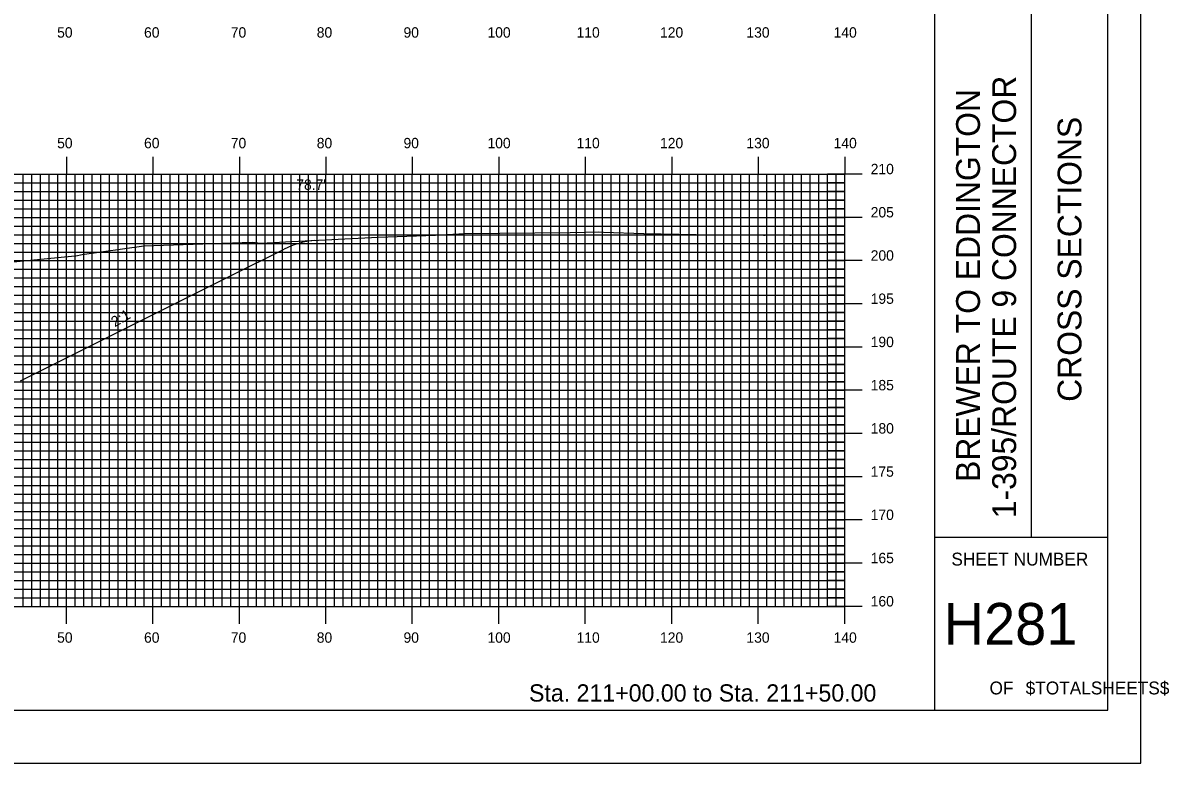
# Model space of a CAD drawing. Extents: x 1794846 to 1795189, y 442591 to 442811.
# Drawn here: x 1795056.8 to 1795189.3, y 442590.5 to 442676.2 of the extents above; entities that cross this region are included whole.
import ezdxf

# ---------------------------------------------------------------- set-up
doc = ezdxf.new("R2010")
doc.units = 0
for name, color, linetype in [('ANNOTATION', 7, 'Continuous'), ('BORDER', 7, 'Continuous'), ('D_Roadway_Centerline', 7, 'Continuous'), ('D_Roadway_SlopeLines', 7, 'Continuous'), ('D_Text_Standard', 7, 'Continuous'), ('H_V ANNOTATION', 7, 'Continuous'), ('MAJOR', 7, 'Continuous'), ('MINOR', 7, 'Continuous'), ('PLOT BOUNDARY', 7, 'Continuous'), ('S_Roadway_Centerline', 7, 'Continuous')]:
    doc.layers.add(name, color=color, linetype=linetype)

msp = doc.modelspace()

# ---------------------------------------------------------------- linework, layer by layer
at = {"layer": 'BORDER'}
for p, q in [((1795162.25, 442596.67), (1795162.25, 442806.67)), ((1795173.43, 442616.67), (1795173.43, 442686.67)), ((1795162.25, 442616.67), (1795182.25, 442616.67))]:
    msp.add_line(p, q, dxfattribs=at)
msp.add_lwpolyline([(1794862.25, 442596.67), (1795182.25, 442596.67), (1795182.25, 442806.67), (1794862.25, 442806.67)], close=True, dxfattribs=at)
at = {"layer": 'D_Roadway_Centerline'}
msp.add_arc((1795091.51, 442641.06), 10, 95.4173, 116.5651, dxfattribs=at)
at = {"layer": 'D_Roadway_SlopeLines'}
for p, q in [((1795080.92, 442646.94), (1795087.03, 442650)), ((1795056.56, 442634.77), (1795080.92, 442646.94))]:
    msp.add_line(p, q, dxfattribs=at)
at = {"layer": 'MAJOR'}
for p, q in [((1795061.85, 442660.67), (1795061.85, 442658.67)), ((1795071.85, 442660.67), (1795071.85, 442658.67)), ((1795081.85, 442660.67), (1795081.85, 442658.67)), ((1795091.85, 442660.67), (1795091.85, 442658.67)), ((1795101.85, 442660.67), (1795101.85, 442658.67)), ((1795111.85, 442660.67), (1795111.85, 442658.67)), ((1795121.85, 442660.67), (1795121.85, 442658.67)), ((1795131.85, 442660.67), (1795131.85, 442658.67)), ((1795141.85, 442660.67), (1795141.85, 442658.67)), ((1795151.85, 442660.67), (1795151.85, 442658.67)), ((1794871.85, 442658.67), (1795151.85, 442658.67)), ((1794871.85, 442658.67), (1795151.85, 442658.67)), ((1795061.85, 442608.67), (1795061.85, 442658.67)), ((1795071.85, 442608.67), (1795071.85, 442658.67)), ((1795081.85, 442608.67), (1795081.85, 442658.67)), ((1795091.85, 442608.67), (1795091.85, 442658.67)), ((1795101.85, 442608.67), (1795101.85, 442658.67)), ((1795111.85, 442608.67), (1795111.85, 442658.67)), ((1795121.85, 442608.67), (1795121.85, 442658.67)), ((1795131.85, 442608.67), (1795131.85, 442658.67)), ((1795141.85, 442608.67), (1795141.85, 442658.67)), ((1795153.86, 442658.67), (1795149.85, 442658.67)), ((1795151.85, 442608.67), (1795151.85, 442658.67)), ((1795151.85, 442608.67), (1795151.85, 442658.67)), ((1794871.85, 442653.67), (1795151.85, 442653.67)), ((1795153.86, 442653.67), (1795149.85, 442653.67)), ((1794871.85, 442648.67), (1795151.85, 442648.67)), ((1795153.86, 442648.67), (1795149.85, 442648.67)), ((1794871.85, 442643.67), (1795151.85, 442643.67)), ((1795153.86, 442643.67), (1795149.85, 442643.67)), ((1794871.85, 442638.67), (1795151.85, 442638.67)), ((1795153.86, 442638.67), (1795149.85, 442638.67)), ((1794871.85, 442633.67), (1795151.85, 442633.67)), ((1795153.86, 442633.67), (1795149.85, 442633.67)), ((1794871.85, 442628.67), (1795151.85, 442628.67)), ((1795153.86, 442628.67), (1795149.85, 442628.67)), ((1794871.85, 442623.67), (1795151.85, 442623.67)), ((1795153.86, 442623.67), (1795149.85, 442623.67)), ((1794871.85, 442618.67), (1795151.85, 442618.67)), ((1795153.86, 442618.67), (1795149.85, 442618.67)), ((1794871.85, 442613.67), (1795151.85, 442613.67)), ((1795153.86, 442613.67), (1795149.85, 442613.67)), ((1794871.85, 442608.67), (1795151.85, 442608.67)), ((1794871.85, 442608.67), (1795151.85, 442608.67)), ((1795061.85, 442606.66), (1795061.85, 442608.67)), ((1795071.85, 442606.66), (1795071.85, 442608.67)), ((1795081.85, 442606.66), (1795081.85, 442608.67)), ((1795091.85, 442606.66), (1795091.85, 442608.67)), ((1795101.85, 442606.66), (1795101.85, 442608.67)), ((1795111.85, 442606.66), (1795111.85, 442608.67)), ((1795121.85, 442606.66), (1795121.85, 442608.67)), ((1795131.85, 442606.66), (1795131.85, 442608.67)), ((1795141.85, 442606.66), (1795141.85, 442608.67)), ((1795153.86, 442608.67), (1795149.85, 442608.67)), ((1795151.85, 442606.66), (1795151.85, 442608.67))]:
    msp.add_line(p, q, dxfattribs=at)
at = {"layer": 'MINOR'}
for p, q in [((1795056.85, 442608.67), (1795056.85, 442658.67)), ((1795057.85, 442608.67), (1795057.85, 442658.67)), ((1795058.85, 442608.67), (1795058.85, 442658.67)), ((1795059.85, 442608.67), (1795059.85, 442658.67)), ((1795060.85, 442608.67), (1795060.85, 442658.67)), ((1795062.85, 442608.67), (1795062.85, 442658.67)), ((1795063.85, 442608.67), (1795063.85, 442658.67)), ((1795064.85, 442608.67), (1795064.85, 442658.67)), ((1795065.85, 442608.67), (1795065.85, 442658.67)), ((1795066.85, 442608.67), (1795066.85, 442658.67)), ((1795067.85, 442608.67), (1795067.85, 442658.67)), ((1795068.85, 442608.67), (1795068.85, 442658.67)), ((1795069.85, 442608.67), (1795069.85, 442658.67)), ((1795070.85, 442608.67), (1795070.85, 442658.67)), ((1795072.85, 442608.67), (1795072.85, 442658.67)), ((1795073.85, 442608.67), (1795073.85, 442658.67)), ((1795074.85, 442608.67), (1795074.85, 442658.67)), ((1795075.85, 442608.67), (1795075.85, 442658.67)), ((1795076.85, 442608.67), (1795076.85, 442658.67)), ((1795077.85, 442608.67), (1795077.85, 442658.67)), ((1795078.85, 442608.67), (1795078.85, 442658.67)), ((1795079.85, 442608.67), (1795079.85, 442658.67)), ((1795080.85, 442608.67), (1795080.85, 442658.67)), ((1795082.85, 442608.67), (1795082.85, 442658.67)), ((1795083.85, 442608.67), (1795083.85, 442658.67)), ((1795084.85, 442608.67), (1795084.85, 442658.67)), ((1795085.85, 442608.67), (1795085.85, 442658.67)), ((1795086.85, 442608.67), (1795086.85, 442658.67)), ((1795087.85, 442608.67), (1795087.85, 442658.67)), ((1795088.85, 442608.67), (1795088.85, 442658.67)), ((1795089.85, 442608.67), (1795089.85, 442658.67)), ((1795090.85, 442608.67), (1795090.85, 442658.67)), ((1795092.85, 442608.67), (1795092.85, 442658.67)), ((1795093.85, 442608.67), (1795093.85, 442658.67)), ((1795094.85, 442608.67), (1795094.85, 442658.67)), ((1795095.85, 442608.67), (1795095.85, 442658.67)), ((1795096.85, 442608.67), (1795096.85, 442658.67)), ((1795097.85, 442608.67), (1795097.85, 442658.67)), ((1795098.85, 442608.67), (1795098.85, 442658.67)), ((1795099.85, 442608.67), (1795099.85, 442658.67)), ((1795100.85, 442608.67), (1795100.85, 442658.67)), ((1795102.85, 442608.67), (1795102.85, 442658.67)), ((1795103.85, 442608.67), (1795103.85, 442658.67)), ((1795104.85, 442608.67), (1795104.85, 442658.67)), ((1795105.85, 442608.67), (1795105.85, 442658.67)), ((1795106.85, 442608.67), (1795106.85, 442658.67)), ((1795107.85, 442608.67), (1795107.85, 442658.67)), ((1795108.85, 442608.67), (1795108.85, 442658.67)), ((1795109.85, 442608.67), (1795109.85, 442658.67)), ((1795110.85, 442608.67), (1795110.85, 442658.67)), ((1795112.85, 442608.67), (1795112.85, 442658.67)), ((1795113.85, 442608.67), (1795113.85, 442658.67)), ((1795114.85, 442608.67), (1795114.85, 442658.67)), ((1795115.85, 442608.67), (1795115.85, 442658.67)), ((1795116.85, 442608.67), (1795116.85, 442658.67)), ((1795117.85, 442608.67), (1795117.85, 442658.67)), ((1795118.85, 442608.67), (1795118.85, 442658.67)), ((1795119.85, 442608.67), (1795119.85, 442658.67)), ((1795120.85, 442608.67), (1795120.85, 442658.67)), ((1795122.85, 442608.67), (1795122.85, 442658.67)), ((1795123.85, 442608.67), (1795123.85, 442658.67)), ((1795124.85, 442608.67), (1795124.85, 442658.67)), ((1795125.85, 442608.67), (1795125.85, 442658.67)), ((1795126.85, 442608.67), (1795126.85, 442658.67)), ((1795127.85, 442608.67), (1795127.85, 442658.67)), ((1795128.85, 442608.67), (1795128.85, 442658.67)), ((1795129.85, 442608.67), (1795129.85, 442658.67)), ((1795130.85, 442608.67), (1795130.85, 442658.67)), ((1795132.85, 442608.67), (1795132.85, 442658.67)), ((1795133.85, 442608.67), (1795133.85, 442658.67)), ((1795134.85, 442608.67), (1795134.85, 442658.67)), ((1795135.85, 442608.67), (1795135.85, 442658.67)), ((1795136.85, 442608.67), (1795136.85, 442658.67)), ((1795137.85, 442608.67), (1795137.85, 442658.67)), ((1795138.85, 442608.67), (1795138.85, 442658.67)), ((1795139.85, 442608.67), (1795139.85, 442658.67)), ((1795140.85, 442608.67), (1795140.85, 442658.67)), ((1795142.85, 442608.67), (1795142.85, 442658.67)), ((1795143.85, 442608.67), (1795143.85, 442658.67)), ((1795144.85, 442608.67), (1795144.85, 442658.67)), ((1795145.85, 442608.67), (1795145.85, 442658.67)), ((1795146.85, 442608.67), (1795146.85, 442658.67)), ((1795147.85, 442608.67), (1795147.85, 442658.67)), ((1795148.85, 442608.67), (1795148.85, 442658.67)), ((1795149.85, 442608.67), (1795149.85, 442658.67)), ((1795150.85, 442608.67), (1795150.85, 442658.67)), ((1794871.85, 442657.67), (1795151.85, 442657.67)), ((1794871.85, 442656.67), (1795151.85, 442656.67)), ((1795151.85, 442657.67), (1795149.85, 442657.67)), ((1795151.85, 442656.67), (1795149.85, 442656.67)), ((1794871.85, 442655.67), (1795151.85, 442655.67)), ((1795151.85, 442655.67), (1795149.85, 442655.67)), ((1794871.85, 442654.67), (1795151.85, 442654.67)), ((1795151.85, 442654.67), (1795149.85, 442654.67)), ((1794871.85, 442652.67), (1795151.85, 442652.67)), ((1795151.85, 442652.67), (1795149.85, 442652.67)), ((1794871.85, 442651.67), (1795151.85, 442651.67)), ((1795151.85, 442651.67), (1795149.85, 442651.67)), ((1794871.85, 442650.67), (1795151.85, 442650.67)), ((1795151.85, 442650.67), (1795149.85, 442650.67)), ((1794871.85, 442649.67), (1795151.85, 442649.67)), ((1795151.85, 442649.67), (1795149.85, 442649.67)), ((1794871.85, 442647.67), (1795151.85, 442647.67)), ((1795151.85, 442647.67), (1795149.85, 442647.67)), ((1794871.85, 442646.67), (1795151.85, 442646.67)), ((1795151.85, 442646.67), (1795149.85, 442646.67)), ((1794871.85, 442645.67), (1795151.85, 442645.67)), ((1795151.85, 442645.67), (1795149.85, 442645.67)), ((1794871.85, 442644.67), (1795151.85, 442644.67)), ((1795151.85, 442644.67), (1795149.85, 442644.67)), ((1794871.85, 442642.67), (1795151.85, 442642.67)), ((1795151.85, 442642.67), (1795149.85, 442642.67)), ((1794871.85, 442641.67), (1795151.85, 442641.67)), ((1795151.85, 442641.67), (1795149.85, 442641.67)), ((1794871.85, 442640.67), (1795151.85, 442640.67)), ((1794871.85, 442639.67), (1795151.85, 442639.67)), ((1795151.85, 442640.67), (1795149.85, 442640.67)), ((1795151.85, 442639.67), (1795149.85, 442639.67)), ((1794871.85, 442637.67), (1795151.85, 442637.67)), ((1795151.85, 442637.67), (1795149.85, 442637.67)), ((1794871.85, 442636.67), (1795151.85, 442636.67)), ((1794871.85, 442635.67), (1795151.85, 442635.67)), ((1795151.85, 442636.67), (1795149.85, 442636.67)), ((1795151.85, 442635.67), (1795149.85, 442635.67)), ((1794871.85, 442634.67), (1795151.85, 442634.67)), ((1795151.85, 442634.67), (1795149.85, 442634.67)), ((1794871.85, 442632.67), (1795151.85, 442632.67)), ((1794871.85, 442631.67), (1795151.85, 442631.67)), ((1795151.85, 442632.67), (1795149.85, 442632.67)), ((1795151.85, 442631.67), (1795149.85, 442631.67)), ((1794871.85, 442630.67), (1795151.85, 442630.67)), ((1795151.85, 442630.67), (1795149.85, 442630.67)), ((1794871.85, 442629.67), (1795151.85, 442629.67)), ((1795151.85, 442629.67), (1795149.85, 442629.67)), ((1794871.85, 442627.67), (1795151.85, 442627.67)), ((1795151.85, 442627.67), (1795149.85, 442627.67)), ((1794871.85, 442626.67), (1795151.85, 442626.67)), ((1795151.85, 442626.67), (1795149.85, 442626.67)), ((1794871.85, 442625.67), (1795151.85, 442625.67)), ((1795151.85, 442625.67), (1795149.85, 442625.67)), ((1794871.85, 442624.67), (1795151.85, 442624.67)), ((1795151.85, 442624.67), (1795149.85, 442624.67)), ((1794871.85, 442622.67), (1795151.85, 442622.67)), ((1795151.85, 442622.67), (1795149.85, 442622.67)), ((1794871.85, 442621.67), (1795151.85, 442621.67)), ((1795151.85, 442621.67), (1795149.85, 442621.67)), ((1794871.85, 442620.67), (1795151.85, 442620.67)), ((1794871.85, 442619.67), (1795151.85, 442619.67)), ((1795151.85, 442620.67), (1795149.85, 442620.67)), ((1795151.85, 442619.67), (1795149.85, 442619.67)), ((1794871.85, 442617.67), (1795151.85, 442617.67)), ((1795151.85, 442617.67), (1795149.85, 442617.67)), ((1794871.85, 442616.67), (1795151.85, 442616.67)), ((1794871.85, 442615.67), (1795151.85, 442615.67)), ((1795151.85, 442616.67), (1795149.85, 442616.67)), ((1795151.85, 442615.67), (1795149.85, 442615.67)), ((1794871.85, 442614.67), (1795151.85, 442614.67)), ((1795151.85, 442614.67), (1795149.85, 442614.67)), ((1794871.85, 442612.67), (1795151.85, 442612.67)), ((1794871.85, 442611.67), (1795151.85, 442611.67)), ((1795151.85, 442612.67), (1795149.85, 442612.67)), ((1795151.85, 442611.67), (1795149.85, 442611.67)), ((1794871.85, 442610.67), (1795151.85, 442610.67)), ((1795151.85, 442610.67), (1795149.85, 442610.67)), ((1794871.85, 442609.67), (1795151.85, 442609.67)), ((1795151.85, 442609.67), (1795149.85, 442609.67))]:
    msp.add_line(p, q, dxfattribs=at)
at = {"layer": 'PLOT BOUNDARY'}
msp.add_lwpolyline([(1794846.07, 442590.55), (1795186.07, 442590.55), (1795186.07, 442810.55), (1794846.07, 442810.55)], close=True, dxfattribs=at)
at = {"layer": 'S_Roadway_Centerline'}
msp.add_lwpolyline([(1795054.13, 442648.38), (1795062.84, 442649.21), (1795062.93, 442649.23), (1795063.68, 442649.39), (1795070.81, 442650.4), (1795083.33, 442650.79), (1795084.32, 442650.71), (1795087.92, 442650.88), (1795097.89, 442651.37), (1795104.53, 442651.63), (1795107.88, 442651.83), (1795120.11, 442651.93), (1795123.42, 442652), (1795123.95, 442651.96), (1795128.61, 442651.82), (1795134.66, 442651.71), (1795138.49, 442651.66), (1795139.73, 442651.66), (1795141.1, 442651.64), (1795142.47, 442651.63), (1795142.63, 442651.63), (1795144.77, 442651.64), (1795144.82, 442651.64), (1795145.51, 442651.63), (1795145.67, 442651.63), (1795147.55, 442651.64), (1795151.85, 442651.68)], dxfattribs=at)

# ---------------------------------------------------------------- texts
at = {"layer": 'ANNOTATION'}
msp.add_text('2:1', height=1.2, rotation=29.7449, dxfattribs=at).set_placement((1795067.45, 442640.96))
msp.add_text('2:1', height=1.2, rotation=29.7449, dxfattribs=at).set_placement((1795067.45, 442640.96))
at = {"layer": 'BORDER'}
for s, p in [('1-395/ROUTE 9 CONNECTOR', (1795171.66, 442618.87)), ('BREWER TO EDDINGTON', (1795167.48, 442623.07)), ('CROSS SECTIONS', (1795179.22, 442632.34))]:
    msp.add_text(s, height=2.7557, rotation=90, dxfattribs=at).set_placement(p)
for s, height, p in [('SHEET NUMBER', 1.4905, (1795164.18, 442613.4)), ('H281', 4.839, (1795163.28, 442604.23)), ('OF', 1.491, (1795168.59, 442598.49)), ('$TOTALSHEETS$', 1.4905, (1795172.77, 442598.49))]:
    msp.add_text(s, height=height, dxfattribs=at).set_placement(p)
at = {"layer": 'D_Text_Standard'}
msp.add_text("78.7'", height=1.2, dxfattribs=at).set_placement((1795088.43, 442656.86))
at = {"layer": 'H_V ANNOTATION'}
for s, height, p in [('50', 1.2, (1795060.78, 442674.47)), ('60', 1.2, (1795070.83, 442674.47)), ('70', 1.2, (1795080.86, 442674.47)), ('80', 1.2, (1795090.8, 442674.47)), ('90', 1.2, (1795100.83, 442674.47)), ('100', 1.2, (1795110.54, 442674.47)), ('110', 1.2, (1795120.84, 442674.47)), ('120', 1.2, (1795130.49, 442674.47)), ('130', 1.2, (1795140.48, 442674.47)), ('140', 1.2, (1795150.56, 442674.47)), ('50', 1.2, (1795060.78, 442661.67)), ('60', 1.2, (1795070.83, 442661.67)), ('70', 1.2, (1795080.86, 442661.67)), ('80', 1.2, (1795090.8, 442661.67)), ('90', 1.2, (1795100.83, 442661.67)), ('100', 1.2, (1795110.54, 442661.67)), ('110', 1.2, (1795120.84, 442661.67)), ('120', 1.2, (1795130.49, 442661.67)), ('130', 1.2, (1795140.48, 442661.67)), ('140', 1.2, (1795150.56, 442661.67)), ('210', 1.2, (1795154.85, 442658.67)), ('205', 1.2, (1795154.85, 442653.67)), ('200', 1.2, (1795154.85, 442648.67)), ('195', 1.2, (1795154.85, 442643.67)), ('190', 1.2, (1795154.85, 442638.67)), ('185', 1.2, (1795154.85, 442633.67)), ('180', 1.2, (1795154.85, 442628.67)), ('175', 1.2, (1795154.85, 442623.67)), ('170', 1.2, (1795154.85, 442618.67)), ('165', 1.2, (1795154.85, 442613.67)), ('160', 1.2, (1795154.85, 442608.67)), ('50', 1.2, (1795060.78, 442604.47)), ('60', 1.2, (1795070.83, 442604.47)), ('70', 1.2, (1795080.86, 442604.47)), ('80', 1.2, (1795090.8, 442604.47)), ('90', 1.2, (1795100.83, 442604.47)), ('100', 1.2, (1795110.54, 442604.47)), ('110', 1.2, (1795120.84, 442604.47)), ('120', 1.2, (1795130.49, 442604.47)), ('130', 1.2, (1795140.48, 442604.47)), ('140', 1.2, (1795150.56, 442604.47)), ('Sta. 211+00.00 to Sta. 211+50.00', 2.0004, (1795115.34, 442597.66))]:
    msp.add_text(s, height=height, dxfattribs=at).set_placement(p)

doc.saveas('drawing.dxf')
